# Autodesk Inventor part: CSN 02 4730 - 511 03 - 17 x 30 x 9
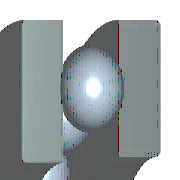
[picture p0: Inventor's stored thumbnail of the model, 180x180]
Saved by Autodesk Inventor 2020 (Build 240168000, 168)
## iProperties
Created: 2019-01
Part Number: CSN 02 4730 - 511 03 - 17 x 30 x 9
Material: Ocel, měkká
Description: Axiální kuličková ložiska jedno- a obousměrná
Document SubType Name: Modeling
Standard: CSN 02 4730
Designer: doma
Standards Organization: CSN
Language: cs-CZ
Size Designation: 511 03 - 17 x 30 x 9
Categories: <MemberInstance><Categories><Category DisplayName="Součásti hřídele" InternalName="7f7aeb1f-a693-4053-b835-cee3144e0d98" Mnemonic="SHFT"><Category DisplayName="
Density: 7.85 g/cm^3
Appearance: Pololeštěná
IsCustomPart: 0
Author: doma
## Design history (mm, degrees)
sketch "Náčrt1" dims "d3" = 3.96 (= 0.44 x KB)
  geometry: L1 (4.5, 10.02)-(4.5, 13.98); L2 (6.48, 12)-(2.52, 12); L3 (2.7, 15)-(0, 15); L4 (2.7, 8.5)-(0, 8.5); L5 (6.3, 12.825)-(6.3, 15); L6 (6.3, 15)-(9, 15); L7 (9, 15)-(9, 9); L8 (9, 9)-(6.3, 9); L9 (6.3, 9)-(6.3, 11.175); L10 (2.7, 15)-(2.7, 12.825); L11 (2.7, 11.175)-(2.7, 8.5); L12 (-1.8, 0)-(10.8, 0) reference; L13 (0, -0.022)-(0, 5.522) reference; 1 further point
  constraints: 22 end point, 5 perpendicular, 2 equal length, 2 midpoint, 2 parallel, 2 point on line, 1 collinear, 10 other
  dimensions: "d8" = 3.6 diameter of L11 L1 (= 0.4 x KB); "d11" = 17 diameter of L4 L12 (= WD); "d12" = 18 diameter of L8 L12 (= KAD1); "d13" = 30 diameter of L3 L12 (= KID1); "d14" = 30 diameter of L6 L12 (= BD); "d15" = 24 diameter of point (4.5, 12) L12 (= 0.5 x KID1 + 0.5 x KAD1); "d16" = 4.5 distance from line of point (4.5, 12) L13 (= 0.5 x KB); "d18" = 9 distance between parallel lines of L7 L13 (= KB)
revolve "Těleso" stored, may be unused: angle "d9" = 90 deg
revolve "Kulička" stored, may be unused: angle "d10" = 90 deg
pattern_circular "Kuličky" dims angle "d2" = 360 deg
body "Solid1"
fillet "Zaoblení1" dims "d4" = 0.3 (= KRS)
fillet "Zaoblení2" dims "d5" = 0.3 (= KRS)
other parameters: "WD" = 17 [user parameter; used in 2 equation terms], "KAD1" = 18 [user parameter; used in 3 equation terms], "KID1" = 30 [user parameter; used in 3 equation terms], "BD" = 30 [user parameter; used in 2 equation terms], "KB" = 9 [user parameter; used in 6 equation terms], "KRS" = 0.3 [user parameter; used in 2 equation terms], "d0" = 1.8 (= 0.2 x KB), "d6" = 0, "d7" = 0, "d19" = 0, "d41" = 0, "d42" = 0, "WR" = 8.5 (= 0.5 x WD) [user parameter], "BC" = 9750000 [user parameter], "BBA" = 90 deg [user parameter], "BC0" = 1.66e+07 [user parameter], "BR" = 15 (= 0.5 x BD) [user parameter]
